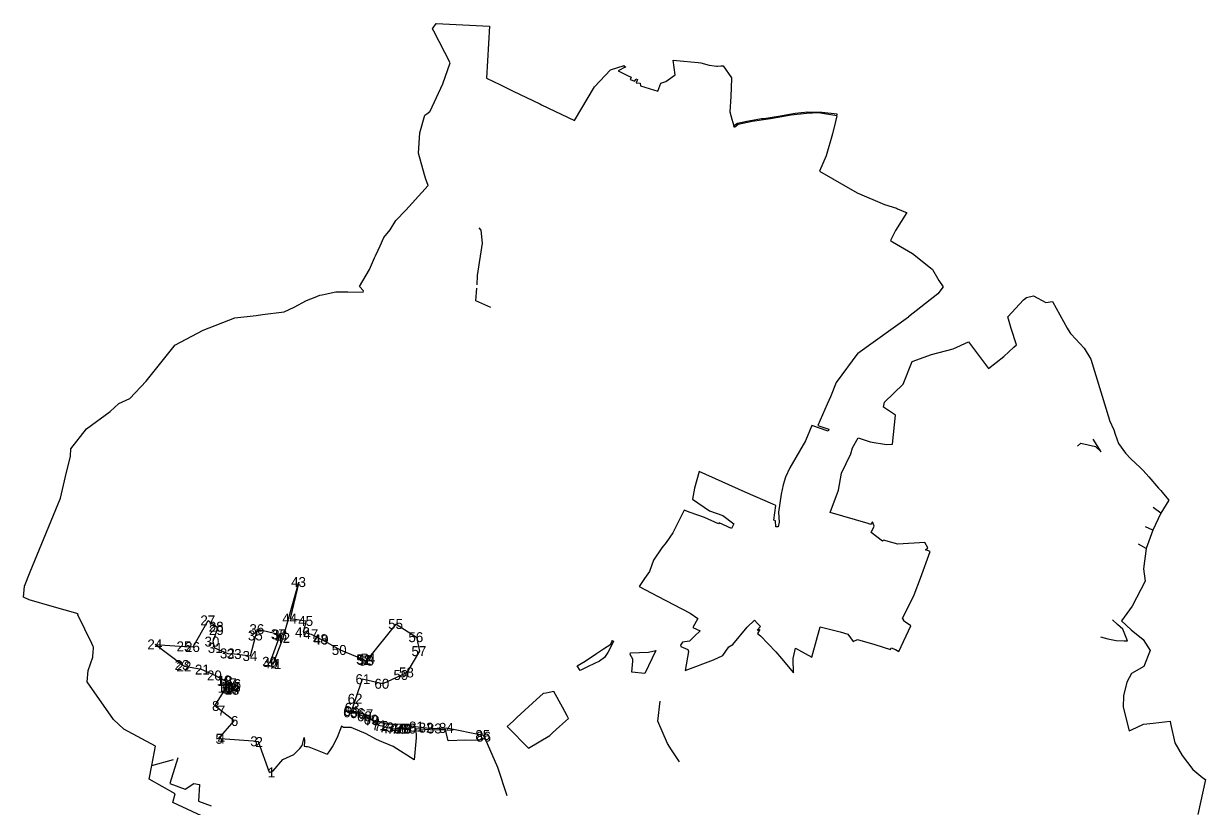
# Model space of a CAD drawing. Extents: x -646407 to -644037, y -1083141 to -1080703.
# Drawn here: x -646407 to -644040, y -1082271 to -1080703 of the extents above; entities that cross this region are included whole.
import ezdxf

# ---------------------------------------------------------------- set-up
doc = ezdxf.new("R2010")
doc.units = 0
for name, color, linetype in [('LES_ZV', 7, 'Continuous'), ('Level 255', 7, 'Continuous'), ('OVNE_PRE', 7, 'Continuous'), ('OVNE_SET', 7, 'Continuous'), ('OVNI_SET', 7, 'Continuous'), ('TRV_ZV', 7, 'Continuous')]:
    doc.layers.add(name, color=color, linetype=linetype)

msp = doc.modelspace()

# ---------------------------------------------------------------- linework, layer by layer
at = {"layer": 'LES_ZV'}
for p, q in [((-644129.7, -1081683.4), (-644145.1, -1081672.1)), ((-644145.6, -1081717.6), (-644160.1, -1081710.8)), ((-644159.3, -1081754.5), (-644174, -1081745.6)), ((-646150.1, -1082189.3), (-646106.9, -1082177.1))]:
    msp.add_line(p, q, dxfattribs=at)
for points in [[(-645498.6, -1081225.9), (-645497.9, -1081207.4), (-645487.7, -1081142.7), (-645490.8, -1081116.5), (-645494.5, -1081112)], [(-645471, -1081271.4), (-645501.5, -1081258.2), (-645499.2, -1081233.1)], [(-644296.8, -1081549.5), (-644289.6, -1081543.7), (-644260.7, -1081549.9), (-644249.1, -1081560.6), (-644265, -1081535.3)], [(-644250.3, -1081931.7), (-644235.8, -1081935.8), (-644219, -1081939.1), (-644202.8, -1081939.6), (-644196.1, -1081939.3), (-644205.9, -1081916.5), (-644216.1, -1081906.6), (-644226.6, -1081897.7)], [(-645093.3, -1082182.2), (-645109.5, -1082157.9), (-645117.7, -1082145.4), (-645136.6, -1082100.5), (-645132.1, -1082060.8)], [(-645438.3, -1082250.5), (-645457.2, -1082193.6), (-645482.8, -1082135.1)], [(-646098, -1082174.2), (-646114.1, -1082225.5), (-646083.2, -1082236.8), (-646065.6, -1082225.3), (-646054.4, -1082227.8), (-646056.2, -1082261.1), (-646030.9, -1082270.4)]]:
    msp.add_lwpolyline(points, dxfattribs=at)
at = {"layer": 'Level 255'}
msp.add_line((-644780.9, -1080898.5), (-644780.9, -1080898.5), dxfattribs=at)
at = {"layer": 'OVNE_PRE'}
for points in [[(-646268.1, -1081972.1), (-646267.9, -1081968.8), (-646267.7, -1081964.6), (-646267, -1081952.2), (-646267.7, -1081950.8), (-646270.4, -1081945.2), (-646298.1, -1081887.4), (-646297.7, -1081885.3), (-646349.3, -1081870.6), (-646395.5, -1081857.4), (-646406.7, -1081852), (-646405, -1081829.7), (-646393.3, -1081801.2), (-646332.8, -1081653.9), (-646322.6, -1081610.5), (-646312.8, -1081569.2), (-646312.3, -1081554.5), (-646281.1, -1081514.7), (-646233.7, -1081479.8), (-646216.1, -1081463.9), (-646194.3, -1081453.9), (-646161, -1081419.1), (-646105.4, -1081348.8), (-646104.1, -1081347.1), (-646047.3, -1081317), (-645984.1, -1081292.5), (-645941.1, -1081287.3), (-645928.6, -1081285.8), (-645885, -1081280.5), (-645865.3, -1081270.6), (-645840, -1081257.8), (-645822.6, -1081250.6), (-645813.9, -1081247.1), (-645809, -1081246.1), (-645802.6, -1081244.7), (-645781.6, -1081240.3), (-645766.9, -1081240.4), (-645757.5, -1081240.4), (-645726.5, -1081240.6), (-645726.3, -1081238.2), (-645734.2, -1081229.2), (-645714.4, -1081195.4), (-645703.9, -1081172.3), (-645701.9, -1081167.9), (-645696.8, -1081156.5), (-645692.9, -1081147.9), (-645685.5, -1081131.4), (-645672.8, -1081116), (-645661.1, -1081097.3), (-645641.1, -1081076.5), (-645628.5, -1081062.5), (-645596.6, -1081027), (-645601.1, -1081014.4), (-645604.1, -1081006), (-645616.3, -1080962.4), (-645613.1, -1080921.7), (-645603, -1080886), (-645599.5, -1080883.4), (-645593.3, -1080878.9), (-645592.9, -1080878.1), (-645567, -1080823.6), (-645552.9, -1080781.2), (-645585.5, -1080717.6), (-645587.7, -1080713.4)], [(-645024.2, -1080787.5), (-645019, -1080787.8), (-645017.5, -1080787.9), (-645010.4, -1080787.4), (-645006.3, -1080787), (-644989.4, -1080811), (-644989.4, -1080812.8), (-644990.6, -1080848.9), (-644992.3, -1080879.7), (-644988.7, -1080894.1), (-644984.7, -1080907.8)], [(-644778.3, -1080887.3), (-644778.5, -1080888.8), (-644778.8, -1080890.2), (-644780.9, -1080898.5), (-644787.2, -1080923.5), (-644800, -1080967.9), (-644813.4, -1080998.3), (-644737.8, -1081041.9), (-644682.6, -1081065.4), (-644659.2, -1081072.7), (-644657.2, -1081073.5), (-644641.2, -1081080.3), (-644640.8, -1081080.4), (-644638.4, -1081081.5), (-644660.7, -1081117.2), (-644670.8, -1081137.6), (-644668.7, -1081138.7), (-644666.9, -1081139.8), (-644626.7, -1081163.1), (-644591.1, -1081191.8), (-644587.7, -1081194.6), (-644587.1, -1081195.7), (-644576.8, -1081212.7), (-644573.8, -1081217.7), (-644565.3, -1081230.2)], [(-646040.6, -1082294.8), (-646107.7, -1082263.4), (-646103.5, -1082246.4), (-646155.4, -1082217), (-646150.1, -1082189.3), (-646142.6, -1082150.4), (-646205.9, -1082116.4), (-646226.7, -1082096.9), (-646279.5, -1082021.6), (-646277.7, -1081998.9), (-646268.1, -1081972.1)]]:
    msp.add_lwpolyline(points, dxfattribs=at)
at = {"layer": 'OVNE_SET'}
for p, q in [((-645587.7, -1080713.4), (-645580.5, -1080702.6)), ((-644736.2, -1081363.2), (-644634.9, -1081290.5)), ((-644220.8, -1081525.2), (-644214.2, -1081544.1))]:
    msp.add_line(p, q, dxfattribs=at)
for points in [[(-645580.5, -1080702.6), (-645474, -1080707.7), (-645480.1, -1080811.9), (-645451.8, -1080825.6)], [(-645451.8, -1080825.6), (-645426.3, -1080837.9), (-645373.3, -1080863.5), (-645369.4, -1080865.4), (-645303.6, -1080897.1), (-645263.7, -1080829.4), (-645231.4, -1080795.1), (-645204.2, -1080786.6), (-645204.2, -1080789.1), (-645200.9, -1080789.3), (-645216.3, -1080797.4), (-645194.9, -1080807.9), (-645192.7, -1080808.7), (-645189.9, -1080809.8), (-645191.9, -1080814.4), (-645182.6, -1080818.2), (-645180.6, -1080813.6), (-645177.3, -1080814.9), (-645180.2, -1080821.3), (-645172.1, -1080822.3), (-645171.8, -1080827.5), (-645136.5, -1080838), (-645130.7, -1080821.7), (-645120.9, -1080818.8), (-645102.2, -1080805.4), (-645106.2, -1080775.9), (-645099.2, -1080776.5), (-645056.2, -1080780.6), (-645050.6, -1080781.3), (-645033.8, -1080786), (-645024.2, -1080787.5)], [(-644778.3, -1080887.3), (-644778, -1080884.2), (-644808.7, -1080880.9), (-644814.9, -1080880.6), (-644836.6, -1080880.1), (-644862, -1080882.5), (-644894.9, -1080888.8), (-644924.6, -1080893.2), (-644929, -1080893.8), (-644958.3, -1080898.9), (-644977.1, -1080902.8), (-644984.7, -1080907.8)], [(-644816.7, -1081508), (-644794.6, -1081515.3), (-644795.9, -1081519.1), (-644828.7, -1081508), (-644841.3, -1081538.8), (-644872.4, -1081593.1), (-644881.2, -1081611.9), (-644885.8, -1081627.2), (-644890.1, -1081645.5), (-644895.2, -1081681.5), (-644893.8, -1081702), (-644896, -1081711.4), (-644900.5, -1081710.9), (-644901.3, -1081699.3), (-644904.5, -1081697.7), (-644900.3, -1081668.5), (-644906.7, -1081665.6), (-644961.6, -1081641.5), (-645054.1, -1081600.2), (-645063.3, -1081633.5), (-645067.4, -1081655.9), (-645033.6, -1081678.9), (-645006.5, -1081688.4), (-644984.7, -1081705.2), (-644989.5, -1081714.2), (-645013.9, -1081703), (-645015, -1081705.4), (-645043.4, -1081692.2), (-645072.2, -1081682.1), (-645083.9, -1081677.6), (-645106.6, -1081722.8), (-645120.1, -1081742.4), (-645128.5, -1081753.1), (-645145.6, -1081777.6), (-645153.5, -1081800.8), (-645163.5, -1081814.9), (-645174.1, -1081830.4), (-645137.2, -1081849.8), (-645072.3, -1081884), (-645056.5, -1081894.5), (-645066.9, -1081912.9), (-645051.7, -1081919.8), (-645063.5, -1081930.1), (-645073.5, -1081940.3), (-645087.6, -1081942.3), (-645091.4, -1081948), (-645091, -1081951), (-645076.6, -1081956.7), (-645075.3, -1081961.2), (-645081.8, -1081999.3), (-645025, -1081977.9), (-645006.5, -1081968.8), (-644994.8, -1081951.5), (-644986.4, -1081946.7), (-644958, -1081912.3), (-644943.5, -1081898.3), (-644937.1, -1081904.6), (-644931.2, -1081910.7), (-644938.2, -1081918.3), (-644932.5, -1081916.6), (-644937.5, -1081924.7), (-644931.5, -1081929.3), (-644900.8, -1081961.7), (-644889.3, -1081975.3), (-644865.4, -1082003.8), (-644865.6, -1081975.2), (-644861.3, -1081954.4), (-644855, -1081957.8), (-644828.1, -1081972.2), (-644811.7, -1081911.5), (-644771.9, -1081921.3), (-644756.3, -1081926.3), (-644745.7, -1081941.1), (-644737.1, -1081936.7), (-644702.3, -1081947), (-644671.2, -1081957.1), (-644669.7, -1081953.5), (-644660.6, -1081956.8), (-644654.2, -1081961.1), (-644630.2, -1081909.3), (-644640.6, -1081902.4), (-644644.8, -1081899.5), (-644643.9, -1081897.7), (-644647.1, -1081895.6), (-644646, -1081893.5), (-644623.3, -1081847.1), (-644611.1, -1081814.2), (-644591.3, -1081760.8), (-644596.6, -1081758.7), (-644601.1, -1081756.9), (-644596.2, -1081753.2), (-644602, -1081742.8), (-644656.3, -1081745.7), (-644668.5, -1081742.3), (-644685.1, -1081737.6), (-644686.8, -1081740), (-644709.5, -1081722.2), (-644703.8, -1081709.7), (-644707.2, -1081701.1), (-644710.8, -1081706.3), (-644715.8, -1081704.4), (-644791.7, -1081682.1), (-644775.3, -1081637.4), (-644769.3, -1081603.7), (-644750.1, -1081565), (-644746.8, -1081552.8), (-644735.6, -1081532.8), (-644711.8, -1081540.6), (-644679, -1081546.2), (-644667.2, -1081545.7), (-644660.8, -1081487.1), (-644684.9, -1081471.4), (-644683.1, -1081461.1), (-644645.4, -1081425.3), (-644627.3, -1081379.8), (-644588.7, -1081365.5), (-644545.1, -1081354.5), (-644514.4, -1081340.1), (-644474.4, -1081393.9), (-644444, -1081369.5), (-644423.7, -1081351.3), (-644418.5, -1081346.7), (-644429.4, -1081313.8), (-644435.7, -1081290), (-644404.8, -1081256), (-644398.7, -1081251.6), (-644384.7, -1081248.5), (-644359.9, -1081261.6), (-644346.7, -1081259.8), (-644317.2, -1081313.1), (-644315.4, -1081316.2)], [(-644565.3, -1081230.2), (-644576.1, -1081244.4), (-644634.9, -1081290.5)], [(-644315.4, -1081316.2), (-644310.6, -1081323.6), (-644309.3, -1081324.8), (-644283.2, -1081353.3), (-644269.5, -1081374.8)], [(-644736.2, -1081363.2), (-644779.8, -1081422), (-644790.8, -1081450.6), (-644797.5, -1081465.6), (-644816.7, -1081508)], [(-644269.5, -1081374.8), (-644249.9, -1081440.7), (-644232.6, -1081497.3), (-644232.2, -1081498.1), (-644223.7, -1081517), (-644220.8, -1081525.2)], [(-644214.2, -1081544.1), (-644200.4, -1081563.7), (-644189.4, -1081574.6), (-644171.1, -1081592.4), (-644165.2, -1081598.2), (-644153.8, -1081611.1), (-644134.2, -1081633.6), (-644131.8, -1081636.3), (-644129.8, -1081638.6), (-644124.1, -1081645.2), (-644113.6, -1081657.5), (-644129.7, -1081683.4), (-644145.6, -1081717.6), (-644159.3, -1081754.5), (-644164.6, -1081795.5), (-644160.8, -1081820.1), (-644187, -1081870.4), (-644208.1, -1081899.8), (-644188.8, -1081917.6), (-644164.7, -1081936.7), (-644151.1, -1081959), (-644163.7, -1081991.3), (-644188.6, -1082005.1), (-644197.8, -1082022.5), (-644204.5, -1082049.7), (-644204.8, -1082072.8), (-644192.9, -1082120), (-644188.1, -1082117.8), (-644164.5, -1082106.7), (-644145, -1082104.5), (-644110.9, -1082100.7), (-644110, -1082105.1), (-644101.9, -1082143.7), (-644087.2, -1082169.2), (-644065.4, -1082197.7), (-644045.5, -1082213.8), (-644040.4, -1082217.6), (-644055.3, -1082287.6)]]:
    msp.add_lwpolyline(points, dxfattribs=at)
at = {"layer": 'OVNI_SET'}
for points in [[(-645914.5, -1082203.3), (-645936.7, -1082142.3), (-645947.1, -1082140.9), (-646012.2, -1082135.9), (-646016.8, -1082135.9), (-645985.3, -1082100.2), (-646012.1, -1082079.2), (-646023.6, -1082070.1), (-646002.7, -1082035.6), (-646001.3, -1082033.7), (-645999.9, -1082031.7), (-645993.8, -1082034.9), (-645988.5, -1082037.6), (-645987.5, -1082035.5), (-645985.8, -1082031.9), (-645984.6, -1082026.4), (-645994.2, -1082024.5), (-646002.2, -1082020.1), (-646004.4, -1082018.9), (-646022.9, -1082009), (-646050.3, -1081997.2), (-646084.7, -1081990.8), (-646088.5, -1081988), (-646143.1, -1081946.7), (-646084.7, -1081950.7), (-646067.2, -1081951.9), (-646036.9, -1081898.7), (-646020.1, -1081911.3), (-646019.8, -1081917.9), (-646027.9, -1081941.1), (-646024.6, -1081953.7), (-645997.9, -1081964.8), (-645984.2, -1081965.9), (-645952.5, -1081969.9), (-645941.8, -1081928.8), (-645938.3, -1081916.2), (-645895.9, -1081926.4), (-645893.2, -1081927), (-645913.1, -1081981.7), (-645910.9, -1081984.5), (-645906.8, -1081986.1), (-645887.1, -1081933.7), (-645855.3, -1081821.8), (-645873, -1081894.9), (-645840.9, -1081899.7), (-645846.8, -1081922.3), (-645830.7, -1081926.2), (-645811.4, -1081936.3), (-645809.9, -1081937.1), (-645773.1, -1081957.9), (-645727.6, -1081976.6), (-645723.7, -1081978.1), (-645719.5, -1081979.4), (-645716.3, -1081975.1), (-645661, -1081905.9), (-645619.9, -1081932.2), (-645614.3, -1081960.2), (-645639.3, -1082002.9), (-645650.2, -1082008.1), (-645687.6, -1082025.6), (-645728.9, -1082016.4), (-645742.1, -1082055.7), (-645748.1, -1082073.9), (-645750.2, -1082080.2), (-645751.1, -1082082.8), (-645737.3, -1082084.5), (-645720.5, -1082086.7), (-645723.4, -1082090.8), (-645710.3, -1082097.5), (-645707.4, -1082098.9), (-645696.1, -1082108.6), (-645689.4, -1082110.2), (-645679.2, -1082113), (-645671.4, -1082114.8), (-645663.3, -1082115.7), (-645654.3, -1082115.8), (-645648.1, -1082115.6), (-645645.7, -1082115.6), (-645643.5, -1082115.6), (-645633.9, -1082115.5), (-645621.7, -1082111.4), (-645600, -1082113.6), (-645583.3, -1082115.2), (-645559.2, -1082114), (-645486.3, -1082128.4), (-645484.3, -1082131.7)], [(-645225.5, -1081940.2), (-645231.2, -1081951.7), (-645236.8, -1081963), (-645243.5, -1081972.9), (-645253.7, -1081980), (-645276.6, -1081991.3), (-645292.3, -1081999.2), (-645298.3, -1081989.6), (-645282.1, -1081980.3), (-645259.9, -1081964.9), (-645245.3, -1081955.3), (-645231.2, -1081946), (-645228.7, -1081941.1), (-645227.7, -1081939), (-645225.5, -1081940.2)], [(-645162.8, -1082005.2), (-645188.6, -1082002.1), (-645188.8, -1082002.1), (-645186.9, -1081980.5), (-645187, -1081976.5), (-645192, -1081966.8), (-645191.2, -1081963.3), (-645155.2, -1081962.1), (-645140.6, -1081958.9), (-645162.8, -1082005.2)], [(-645345, -1082040.8), (-645354.7, -1082042.8), (-645360.4, -1082044.7), (-645366.5, -1082045), (-645379.6, -1082057), (-645419, -1082093), (-645425.6, -1082100.1), (-645432.3, -1082105.9), (-645438.4, -1082111), (-645436.2, -1082113.2), (-645395.9, -1082154.9), (-645353.3, -1082129.1), (-645347.8, -1082124.2), (-645333.6, -1082111.3), (-645315.7, -1082095), (-645318.6, -1082089.6), (-645328, -1082072.2), (-645345, -1082040.8)], [(-645484.3, -1082131.7), (-645482.8, -1082135.1), (-645497, -1082139.5), (-645521.2, -1082138.5), (-645556.9, -1082139.9), (-645560.6, -1082123.4), (-645561.6, -1082118.2), (-645572.3, -1082118.1), (-645583.6, -1082118.8), (-645621.2, -1082115.6), (-645621, -1082134.2), (-645624.9, -1082177.9), (-645666.7, -1082151.6), (-645694, -1082140), (-645701.6, -1082136.8), (-645720.8, -1082125.7), (-645750.8, -1082113.5), (-645766, -1082113.1), (-645770.3, -1082110.9), (-645778.6, -1082133.1), (-645787.5, -1082150.1), (-645794.4, -1082160.1), (-645799.1, -1082167)], [(-645914.5, -1082203.3), (-645906.8, -1082200.2), (-645887.7, -1082177.1), (-645865.5, -1082167.6), (-645853.9, -1082155.2), (-645849.2, -1082149.6), (-645844.8, -1082133.5), (-645844, -1082140.8), (-645844.7, -1082150.8), (-645841.7, -1082151), (-645840.1, -1082151.1), (-645838.5, -1082151.5), (-645835.3, -1082151.8), (-645799.1, -1082167)]]:
    msp.add_lwpolyline(points, dxfattribs=at)
at = {"layer": 'TRV_ZV'}
msp.add_lwpolyline([(-644778.3, -1080887.3), (-644814.8, -1080881.6), (-644839.2, -1080882.7), (-644869.8, -1080885.8), (-644911.5, -1080893.2), (-644947.6, -1080898.7), (-644975.8, -1080905), (-644983.3, -1080910.7), (-644984.7, -1080907.8)], dxfattribs=at)

# ---------------------------------------------------------------- texts
at = {"layer": 'OVNE_SET'}
for s, p in [('43', (-645871.1, -1081831.8)), ('44', (-645888.8, -1081904.9)), ('27', (-646052.8, -1081908.7)), ('28', (-646035.9, -1081921.3)), ('29', (-646035.7, -1081927.9)), ('36', (-645954.6, -1081926.2)), ('45', (-645856.7, -1081909.7)), ('55', (-645676.8, -1081915.9)), ('30', (-646044.5, -1081951.1)), ('35', (-645957.6, -1081938.8)), ('37', (-645911.7, -1081936.4)), ('38', (-645909, -1081937)), ('42', (-645902.9, -1081943.7)), ('46', (-645863.1, -1081932.3)), ('47', (-645846.5, -1081936.2)), ('48', (-645827.3, -1081946.3)), ('49', (-645825.8, -1081947.1)), ('56', (-645636.2, -1081942.2)), ('24', (-646158.9, -1081956.7)), ('25', (-646100.5, -1081960.7)), ('26', (-646083.5, -1081961.9)), ('31', (-646038, -1081963.7)), ('32', (-646013.7, -1081974.8)), ('33', (-646000, -1081975.9)), ('50', (-645789.7, -1081967.9)), ('57', (-645630.1, -1081970.2)), ('23', (-646104.3, -1081998)), ('22', (-646100.6, -1082000.8)), ('34', (-645968.4, -1081979.9)), ('39', (-645928.9, -1081991.7)), ('40', (-645927.5, -1081994.5)), ('41', (-645920.2, -1081996.1)), ('51', (-645740.9, -1081986.6)), ('52', (-645739.5, -1081988.1)), ('53', (-645735.3, -1081989.4)), ('54', (-645732.1, -1081985.1)), ('21', (-646063.7, -1082007.2)), ('20', (-646039.6, -1082019)), ('59', (-645666.1, -1082018.1)), ('58', (-645655.1, -1082012.9)), ('19', (-646020.2, -1082028.9)), ('18', (-646018.1, -1082030.1)), ('10', (-646017.9, -1082043.7)), ('11', (-646013.3, -1082041.7)), ('17', (-646010.1, -1082034.5)), ('12', (-646009.6, -1082044.9)), ('9', (-646008.5, -1082045.6)), ('13', (-646004.3, -1082047.6)), ('14', (-646003.3, -1082045.5)), ('15', (-646001.7, -1082041.9)), ('16', (-646000.9, -1082036.4)), ('61', (-645742.2, -1082026.4)), ('60', (-645704.3, -1082035.6)), ('62', (-645757.9, -1082065.7)), ('8', (-646029.5, -1082080.1)), ('7', (-646017.9, -1082089.2)), ('65', (-645766.9, -1082092.8)), ('64', (-645766.1, -1082090.2)), ('63', (-645764, -1082083.9)), ('66', (-645753.6, -1082094.5)), ('67', (-645736.3, -1082096.7)), ('6', (-645991.7, -1082110.2)), ('68', (-645739.2, -1082100.8)), ('69', (-645726.1, -1082107.5)), ('70', (-645724, -1082108.9)), ('71', (-645709.4, -1082118.6)), ('72', (-645705.2, -1082120.2)), ('73', (-645695.1, -1082123)), ('74', (-645687.3, -1082124.8)), ('75', (-645679.2, -1082125.7)), ('76', (-645670.6, -1082125.8)), ('77', (-645663.9, -1082125.6)), ('78', (-645661.5, -1082125.6)), ('79', (-645659.3, -1082125.6)), ('80', (-645650.5, -1082125.5)), ('81', (-645635, -1082121.4)), ('82', (-645615.8, -1082123.6)), ('83', (-645599.2, -1082125.2)), ('84', (-645575.1, -1082124)), ('85', (-645502.2, -1082138.4)), ('86', (-645500.6, -1082141.7)), ('5', (-646022.6, -1082145.9)), ('4', (-646018.1, -1082145.9)), ('3', (-645952.9, -1082150.9)), ('2', (-645942.5, -1082152.3)), ('1', (-645917.9, -1082213.3))]:
    msp.add_text(s, height=20, dxfattribs=at).set_placement(p)

doc.saveas('drawing.dxf')
